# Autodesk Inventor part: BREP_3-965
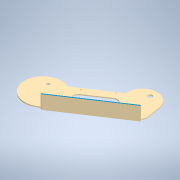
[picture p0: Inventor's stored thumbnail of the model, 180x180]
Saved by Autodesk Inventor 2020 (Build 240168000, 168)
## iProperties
Created: 2017-09
Part Number: BREP_3-965
Material: Or
Document SubType Name: Modeling
Designer: bruno
Density: 19.3 g/cm^3
Appearance: Bleu ciel foncé
Mass: 499.179 g
Surface Area: 276.724 cm^2
Volume: 25.8642 cm^3
Sending System: SolidWorks 2016
Last Author: Prof
Last Saved: 2018-10-03
Author: bruno
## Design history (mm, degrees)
node "Enlèv. mat.-Extru.2"
sketch "Esquisse1"
  geometry: L1 (-67.999, -21.243)-(167.417, -21.243); L2 (167.417, -21.243)-(167.417, -71.771); L3 (167.417, -71.771)-(-67.999, -71.771); L4 (-67.999, -71.771)-(-67.999, -21.243); 1 further point
  constraints: 8 end point, 2 parallel, 1 horizontal, 1 perpendicular
extrude "Extrusion1" cut sketch "Esquisse1" distance "d0" = 100; taper "d1" = 0 deg
node "Solide1"
